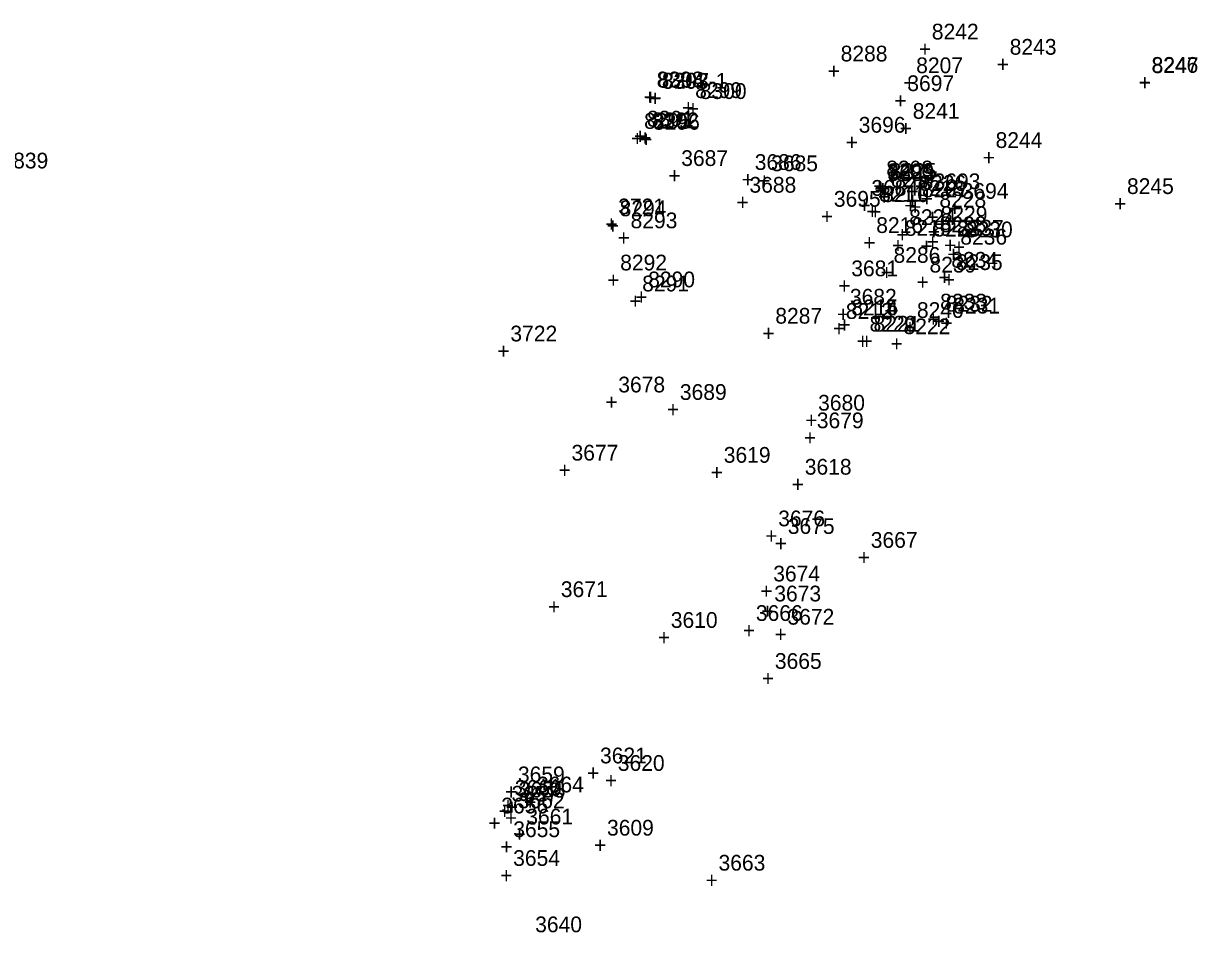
# Model space of a CAD drawing. Extents: x 1136220 to 1137808, y 528804 to 531215.
# Drawn here: x 1137087 to 1137273.5, y 530225.6 to 530370 of the extents above; entities that cross this region are included whole.
import ezdxf

# ---------------------------------------------------------------- set-up
doc = ezdxf.new("R2010")
doc.units = 0
for name, color, linetype in [('S_Buildings', 7, 'Continuous'), ('S_Buildings_Steps_Brick', 7, 'Continuous'), ('S_Curb_Type_1', 7, 'Continuous'), ('S_Drainage_CB', 7, 'Continuous'), ('S_Drainage_Culvert_Top', 7, 'Continuous'), ('S_Drainage_Invert', 7, 'Continuous'), ('S_Drainage_Sump', 7, 'Continuous'), ('S_Ground_Elevation', 7, 'Continuous'), ('S_Ground_LevelString', 7, 'Continuous'), ('S_Ground_SpotElevation', 7, 'Continuous'), ('S_RetWall_Top', 7, 'Continuous'), ('S_Roadway_Centerline', 7, 'Continuous'), ('S_Roadway_Drive_Paved', 7, 'Continuous'), ('S_Roadway_Edge_Pavement', 7, 'Continuous'), ('S_Roadway_Sidewalks', 7, 'Continuous'), ('S_Trees_Decid_Pay', 7, 'Continuous'), ('S_Utilities_Gas_Gate', 7, 'Continuous'), ('S_Utilities_Pole_Power', 7, 'Continuous'), ('S_Utilities_UG_Gas_Line', 7, 'Continuous'), ('S_Utilities_UG_Sanitary_MH', 7, 'Continuous'), ('S_Utilities_UG_Telephone', 7, 'Continuous'), ('S_Utilities_UG_Water_Gate', 7, 'Continuous'), ('S_Utilities_UG_Water_Line', 7, 'Continuous'), ('S_Utilities_UG_Water_MH', 7, 'Continuous')]:
    doc.layers.add(name, color=color, linetype=linetype)

msp = doc.modelspace()

# ---------------------------------------------------------------- texts
at = {"layer": 'S_Buildings'}
for s, p in [('10839', (1137081.68, 530346.96)), ('3721', (1137181.51, 530339.67)), ('+', (1137179.45, 530336.92)), ('3722', (1137164.38, 530319.49)), ('+', (1137162.31, 530316.74)), ('3667', (1137221.62, 530286.71)), ('+', (1137219.56, 530283.96))]:
    msp.add_text(s, height=2.5, dxfattribs=at).set_placement(p)
at = {"layer": 'S_Buildings_Steps_Brick'}
for s, p in [('8304', (1137187.75, 530359.78)), ('8303-1', (1137188.44, 530359.61)), ('+', (1137185.69, 530357.03)), ('+', (1137186.38, 530356.86)), ('8301', (1137186.07, 530353.61)), ('8302', (1137186.86, 530353.35)), ('+', (1137184.01, 530350.86)), ('+', (1137184.8, 530350.6))]:
    msp.add_text(s, height=2.5, dxfattribs=at).set_placement(p)
at = {"layer": 'S_Curb_Type_1'}
for s, p in [('8299', (1137193.73, 530358.14)), ('+', (1137191.66, 530355.39)), ('8209', (1137224.24, 530345.25)), ('+', (1137222.18, 530342.5)), ('8210', (1137223.43, 530341.62)), ('+', (1137221.37, 530338.87)), ('8291', (1137185.32, 530327.43)), ('+', (1137183.26, 530324.68)), ('8213', (1137217.66, 530323.07)), ('+', (1137215.6, 530320.32))]:
    msp.add_text(s, height=2.5, dxfattribs=at).set_placement(p)
at = {"layer": 'S_Drainage_CB'}
for s, p in [('3657', (1137164.56, 530246.41)), ('+', (1137162.5, 530243.66))]:
    msp.add_text(s, height=2.5, dxfattribs=at).set_placement(p)
at = {"layer": 'S_Drainage_Culvert_Top'}
for s, p in [('3659', (1137165.58, 530249.48)), ('+', (1137163.52, 530246.73)), ('3661', (1137166.91, 530242.78)), ('+', (1137164.85, 530240.03))]:
    msp.add_text(s, height=2.5, dxfattribs=at).set_placement(p)
at = {"layer": 'S_Drainage_Invert'}
for s, p in [('3660', (1137165.09, 530247.33)), ('3662', (1137165.56, 530245.35)), ('+', (1137163.03, 530244.58)), ('+', (1137163.5, 530242.6))]:
    msp.add_text(s, height=2.5, dxfattribs=at).set_placement(p)
at = {"layer": 'S_Drainage_Sump'}
for s, p in [('3658', (1137165.69, 530247.06)), ('+', (1137163.63, 530244.31))]:
    msp.add_text(s, height=2.5, dxfattribs=at).set_placement(p)
at = {"layer": 'S_Ground_Elevation'}
for s, p in [('8217', (1137224.84, 530343.98)), ('8218', (1137229.01, 530342.59)), ('+', (1137222.77, 530341.23)), ('+', (1137226.95, 530339.84)), ('8216', (1137222.49, 530336.71)), ('8219', (1137227.03, 530336.26)), ('8238', (1137232.56, 530336.83)), ('8237', (1137235.31, 530336.29)), ('+', (1137220.43, 530333.96)), ('+', (1137224.97, 530333.51)), ('+', (1137230.49, 530334.08)), ('+', (1137233.25, 530333.54)), ('8234', (1137234.41, 530331.2)), ('8239', (1137230.95, 530330.43)), ('+', (1137228.89, 530327.68)), ('+', (1137232.35, 530328.45)), ('8215', (1137218.53, 530323.65)), ('8240', (1137228.95, 530323.22)), ('8233', (1137232.64, 530324.56)), ('+', (1137230.58, 530321.81)), ('+', (1137216.47, 530320.9)), ('8220', (1137221.43, 530321.05)), ('+', (1137226.89, 530320.47)), ('+', (1137219.37, 530318.3))]:
    msp.add_text(s, height=2.5, dxfattribs=at).set_placement(p)
at = {"layer": 'S_Ground_LevelString'}
for s, p in [('8242', (1137231.32, 530367.44)), ('+', (1137229.26, 530364.69)), ('8243', (1137243.69, 530365.02)), ('+', (1137241.63, 530362.27)), ('8246', (1137266.21, 530362.15)), ('8247', (1137266.25, 530362.09)), ('+', (1137264.15, 530359.4)), ('+', (1137264.19, 530359.34)), ('8241', (1137228.29, 530354.84)), ('+', (1137226.23, 530352.09)), ('8244', (1137241.45, 530350.21)), ('+', (1137239.39, 530347.46)), ('8245', (1137262.32, 530342.9)), ('+', (1137260.25, 530340.15))]:
    msp.add_text(s, height=2.5, dxfattribs=at).set_placement(p)
at = {"layer": 'S_Ground_SpotElevation'}
for s, p in [('3688', (1137202.35, 530343.11)), ('+', (1137200.29, 530340.36)), ('3689', (1137191.3, 530310.2)), ('+', (1137189.24, 530307.45)), ('3664', (1137168.61, 530247.87)), ('+', (1137166.55, 530245.12))]:
    msp.add_text(s, height=2.5, dxfattribs=at).set_placement(p)
at = {"layer": 'S_RetWall_Top'}
for s, p in [('8236', (1137235.84, 530334.86)), ('+', (1137233.78, 530332.11)), ('8235', (1137235.14, 530330.83)), ('+', (1137233.08, 530328.08)), ('8232', (1137233.52, 530324.23)), ('+', (1137231.46, 530321.48))]:
    msp.add_text(s, height=2.5, dxfattribs=at).set_placement(p)
at = {"layer": 'S_Roadway_Centerline'}
for s, p in [('8288', (1137216.84, 530363.95)), ('+', (1137214.78, 530361.2)), ('8287', (1137206.46, 530322.31)), ('+', (1137204.4, 530319.56)), ('3610', (1137189.86, 530274)), ('+', (1137187.8, 530271.25)), ('3609', (1137179.73, 530241.01)), ('+', (1137177.67, 530238.26))]:
    msp.add_text(s, height=2.5, dxfattribs=at).set_placement(p)
at = {"layer": 'S_Roadway_Drive_Paved'}
for s, p in [('8225', (1137224.61, 530345.31)), ('+', (1137222.55, 530342.56)), ('8226', (1137229.34, 530343.4)), ('8227', (1137229.77, 530342.38)), ('+', (1137227.28, 530340.65)), ('8228', (1137232.52, 530340.77)), ('+', (1137227.71, 530339.63)), ('8229', (1137232.72, 530338.44)), ('+', (1137230.45, 530338.02)), ('+', (1137230.66, 530335.69)), ('8230', (1137236.73, 530336.02)), ('+', (1137234.67, 530333.27)), ('8231', (1137234.72, 530323.92)), ('+', (1137232.66, 530321.17))]:
    msp.add_text(s, height=2.5, dxfattribs=at).set_placement(p)
at = {"layer": 'S_Roadway_Edge_Pavement'}
for s, p in [('8207', (1137228.84, 530362.09)), ('+', (1137226.78, 530359.35)), ('8300', (1137194.46, 530357.99)), ('+', (1137192.4, 530355.24)), ('3687', (1137191.52, 530347.35)), ('8208', (1137224.08, 530345.69)), ('+', (1137189.46, 530344.6)), ('3683', (1137224.28, 530344.97)), ('+', (1137222.02, 530342.94)), ('+', (1137222.22, 530342.22)), ('8211', (1137222.95, 530341.67)), ('+', (1137220.89, 530338.92)), ('8290', (1137186.27, 530328.08)), ('3682', (1137218.31, 530325.33)), ('+', (1137184.21, 530325.33)), ('+', (1137216.25, 530322.58)), ('8212', (1137217.66, 530323.06)), ('+', (1137215.6, 530320.31)), ('3678', (1137181.52, 530311.39)), ('+', (1137179.46, 530308.64)), ('3679', (1137213.05, 530305.7)), ('+', (1137210.99, 530302.96)), ('3675', (1137208.44, 530288.92)), ('+', (1137206.37, 530286.17)), ('3674', (1137206.13, 530281.37)), ('3671', (1137172.39, 530278.89)), ('+', (1137204.07, 530278.62)), ('3673', (1137206.3, 530278.2)), ('+', (1137170.33, 530276.14)), ('+', (1137204.24, 530275.45)), ('3672', (1137208.39, 530274.51)), ('+', (1137206.33, 530271.76)), ('3665', (1137206.39, 530267.49)), ('+', (1137204.33, 530264.74)), ('3656', (1137162.94, 530244.53)), ('+', (1137160.88, 530241.78)), ('3655', (1137164.84, 530240.77)), ('+', (1137162.78, 530238.02)), ('3654', (1137164.82, 530236.2)), ('3663', (1137197.44, 530235.45)), ('+', (1137162.76, 530233.45)), ('+', (1137195.38, 530232.7))]:
    msp.add_text(s, height=2.5, dxfattribs=at).set_placement(p)
at = {"layer": 'S_Roadway_Sidewalks'}
for s, p in [('8298', (1137187.62, 530359.83)), ('8297', (1137188.5, 530359.64)), ('+', (1137185.56, 530357.08)), ('+', (1137186.44, 530356.89)), ('8295', (1137185.62, 530353.25)), ('8296', (1137187.03, 530353.11)), ('+', (1137183.56, 530350.5)), ('+', (1137184.97, 530350.36)), ('8294', (1137181.73, 530339.37)), ('+', (1137179.67, 530336.62)), ('8293', (1137183.47, 530337.46)), ('8224', (1137227.72, 530337.97)), ('8223', (1137231.57, 530336.15)), ('+', (1137181.41, 530334.71)), ('+', (1137225.66, 530335.22)), ('+', (1137229.51, 530333.4)), ('8292', (1137181.82, 530330.76)), ('+', (1137179.76, 530328.01)), ('8221', (1137222.06, 530321.05)), ('8222', (1137226.82, 530320.64)), ('+', (1137220, 530318.3)), ('+', (1137224.76, 530317.89))]:
    msp.add_text(s, height=2.5, dxfattribs=at).set_placement(p)
at = {"layer": 'S_Trees_Decid_Pay'}
for s, p in [('8214', (1137218.53, 530323.65)), ('+', (1137216.47, 530320.9))]:
    msp.add_text(s, height=2.5, dxfattribs=at).set_placement(p)
at = {"layer": 'S_Utilities_Gas_Gate'}
for s, p in [('3618', (1137211.14, 530298.33)), ('+', (1137209.07, 530295.58))]:
    msp.add_text(s, height=2.5, dxfattribs=at).set_placement(p)
at = {"layer": 'S_Utilities_Pole_Power'}
for s, p in [('8286', (1137225.24, 530331.97)), ('+', (1137223.18, 530329.22))]:
    msp.add_text(s, height=2.5, dxfattribs=at).set_placement(p)
at = {"layer": 'S_Utilities_UG_Gas_Line'}
for s, p in [('3697', (1137227.43, 530359.24)), ('+', (1137225.37, 530356.49)), ('3681', (1137218.53, 530329.84)), ('+', (1137216.46, 530327.09)), ('3680', (1137213.26, 530308.5)), ('+', (1137211.2, 530305.75)), ('3677', (1137174.09, 530300.57)), ('+', (1137172.02, 530297.82)), ('3676', (1137206.92, 530290.13)), ('+', (1137204.86, 530287.38)), ('3666', (1137203.37, 530275.1)), ('+', (1137201.31, 530272.35)), ('3640', (1137168.32, 530225.66))]:
    msp.add_text(s, height=2.5, dxfattribs=at).set_placement(p)
at = {"layer": 'S_Utilities_UG_Sanitary_MH'}
for s, p in [('3619', (1137198.27, 530300.22)), ('+', (1137196.21, 530297.47))]:
    msp.add_text(s, height=2.5, dxfattribs=at).set_placement(p)
at = {"layer": 'S_Utilities_UG_Telephone'}
for s, p in [('3696', (1137219.71, 530352.64)), ('+', (1137217.65, 530349.89)), ('3695', (1137215.76, 530340.88)), ('+', (1137213.7, 530338.13))]:
    msp.add_text(s, height=2.5, dxfattribs=at).set_placement(p)
at = {"layer": 'S_Utilities_UG_Water_Gate'}
for s, p in [('3685', (1137205.8, 530346.52)), ('3693', (1137231.6, 530343.67)), ('+', (1137203.74, 530343.77)), ('+', (1137229.54, 530340.92)), ('3620', (1137181.44, 530251.29)), ('+', (1137179.38, 530248.54))]:
    msp.add_text(s, height=2.5, dxfattribs=at).set_placement(p)
at = {"layer": 'S_Utilities_UG_Water_Line'}
for s, p in [('3686', (1137203.19, 530346.72)), ('+', (1137201.13, 530343.97)), ('3684', (1137221.72, 530342.62)), ('+', (1137219.66, 530339.87)), ('3621', (1137178.62, 530252.48)), ('+', (1137176.56, 530249.73))]:
    msp.add_text(s, height=2.5, dxfattribs=at).set_placement(p)
at = {"layer": 'S_Utilities_UG_Water_MH'}
for s, p in [('3694', (1137236.06, 530342.14)), ('+', (1137234, 530339.39))]:
    msp.add_text(s, height=2.5, dxfattribs=at).set_placement(p)

doc.saveas('drawing.dxf')
